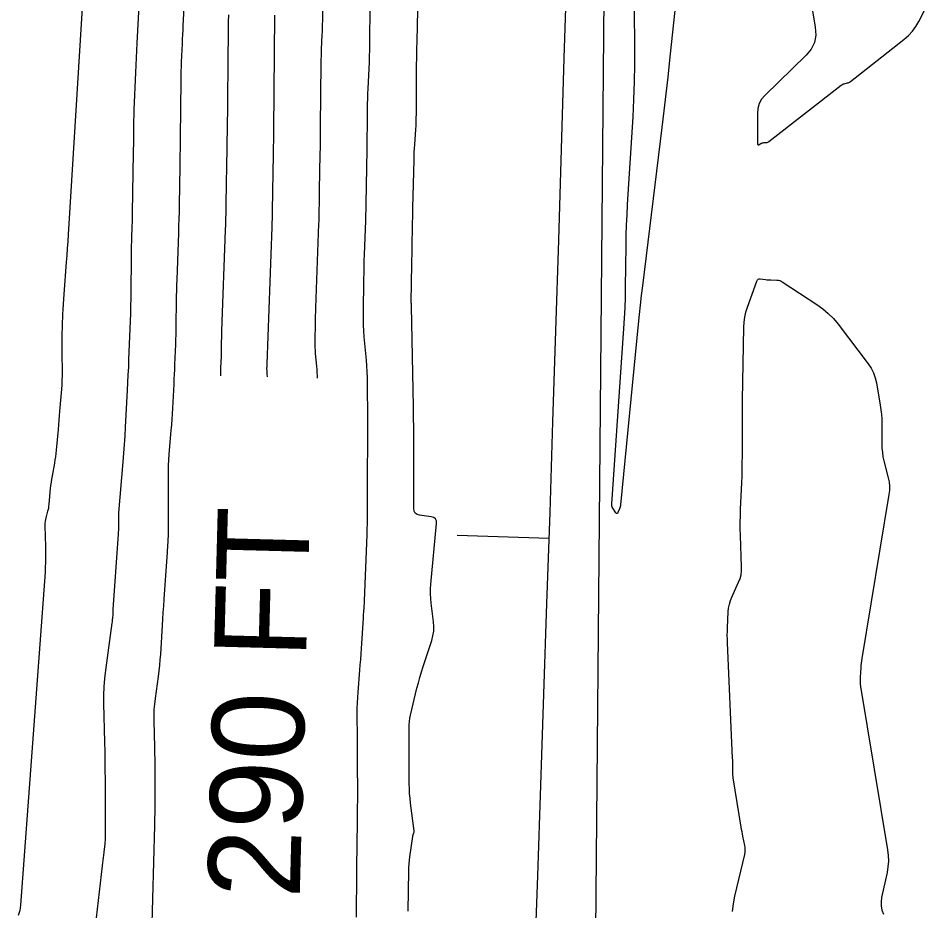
# Model space of a CAD drawing. Extents: x 1768942 to 1774819, y 723037 to 732099.
# Drawn here: x 1770547.7 to 1770607.1, y 731065.2 to 731123.3 of the extents above; entities that cross this region are included whole.
import ezdxf

# ---------------------------------------------------------------- set-up
doc = ezdxf.new("R2010")
doc.units = 0
for name, color, linetype in [('R_Contour Annot', 7, 'Continuous'), ('R_Contours', 7, 'Continuous'), ('R_Horz Alg', 7, 'Continuous')]:
    doc.layers.add(name, color=color, linetype=linetype)

msp = doc.modelspace()

# ---------------------------------------------------------------- linework, layer by layer
at = {"layer": 'R_Contours'}
for points in [[(1770573.122, 731065.186), (1770573.161, 731067.806), (1770573.168, 731068.039), (1770573.182, 731068.271), (1770573.203, 731068.503), (1770573.231, 731068.734), (1770573.41, 731070.056), (1770573.416, 731070.087), (1770573.422, 731070.117), (1770573.431, 731070.147), (1770573.441, 731070.177), (1770573.486, 731070.294), (1770573.495, 731070.324), (1770573.501, 731070.354), (1770573.503, 731070.385), (1770573.501, 731070.415), (1770573.27, 731072.229), (1770573.235, 731072.542), (1770573.21, 731072.856), (1770573.194, 731073.17), (1770573.188, 731073.485), (1770573.182, 731075.423), (1770573.181, 731075.635), (1770573.18, 731075.846), (1770573.179, 731076.058), (1770573.178, 731076.269), (1770573.172, 731077.115), (1770573.177, 731077.326), (1770573.195, 731077.536), (1770573.226, 731077.743), (1770573.269, 731077.95), (1770573.688, 731079.692), (1770573.778, 731080.05), (1770573.876, 731080.406), (1770573.98, 731080.76), (1770574.091, 731081.112), (1770574.649, 731082.812), (1770574.728, 731083.107), (1770574.774, 731083.405), (1770574.786, 731083.706), (1770574.764, 731084.011), (1770574.611, 731085.236), (1770574.581, 731085.542), (1770574.568, 731085.849), (1770574.572, 731086.155), (1770574.592, 731086.463), (1770574.96, 731090.426), (1770574.951, 731090.596), (1770574.891, 731090.724), (1770574.779, 731090.811), (1770574.615, 731090.856), (1770573.856, 731090.954), (1770573.69, 731090.999), (1770573.571, 731091.086), (1770573.501, 731091.215), (1770573.477, 731091.385), (1770573.484, 731093.134), (1770573.485, 731093.49), (1770573.485, 731093.845), (1770573.485, 731094.2), (1770573.484, 731094.556), (1770573.476, 731096.348), (1770573.474, 731096.765), (1770573.47, 731097.182), (1770573.464, 731097.599), (1770573.457, 731098.016), (1770573.333, 731104.563), (1770573.333, 731104.585), (1770573.332, 731104.606), (1770573.33, 731104.627), (1770573.329, 731104.649), (1770573.321, 731104.734), (1770573.319, 731104.756), (1770573.318, 731104.777), (1770573.318, 731104.798), (1770573.318, 731104.82), (1770573.356, 731107.285), (1770573.361, 731107.59), (1770573.366, 731107.895), (1770573.371, 731108.2), (1770573.376, 731108.504), (1770573.396, 731109.723), (1770573.402, 731110.028), (1770573.408, 731110.333), (1770573.414, 731110.638), (1770573.421, 731110.942), (1770573.496, 731114.085), (1770573.504, 731114.332), (1770573.514, 731114.579), (1770573.526, 731114.826), (1770573.542, 731115.073), (1770573.61, 731116.06), (1770573.625, 731116.307), (1770573.636, 731116.554), (1770573.643, 731116.801), (1770573.647, 731117.048), (1770573.662, 731119.699), (1770573.666, 731120.223), (1770573.673, 731120.747), (1770573.682, 731121.272), (1770573.693, 731121.796), (1770573.791, 731125.837)], [(1770590.619, 731125.249), (1770590.129, 731120.565), (1770590.011, 731119.466), (1770589.889, 731118.368), (1770589.761, 731117.27), (1770589.628, 731116.173), (1770588.359, 731105.871), (1770588.284, 731105.251), (1770588.214, 731104.631), (1770588.147, 731104.01), (1770588.085, 731103.388), (1770586.943, 731091.634), (1770586.934, 731091.567), (1770586.92, 731091.501), (1770586.9, 731091.437), (1770586.876, 731091.374), (1770586.767, 731091.125), (1770586.738, 731091.077), (1770586.707, 731091.06), (1770586.673, 731091.072), (1770586.637, 731091.113), (1770586.441, 731091.407), (1770586.402, 731091.476), (1770586.376, 731091.549), (1770586.363, 731091.625), (1770586.362, 731091.705), (1770587.155, 731103.111), (1770587.197, 731103.783), (1770587.229, 731104.454), (1770587.252, 731105.127), (1770587.266, 731105.799), (1770587.301, 731108.491), (1770587.313, 731109.163), (1770587.334, 731109.836), (1770587.364, 731110.508), (1770587.401, 731111.179), (1770587.753, 731116.878), (1770587.813, 731118.01), (1770587.854, 731119.143), (1770587.874, 731120.276), (1770587.875, 731121.41), (1770587.836, 731126.29)], [(1770551.981, 731125.394), (1770550.981, 731109.229), (1770550.952, 731108.774), (1770550.921, 731108.319), (1770550.888, 731107.864), (1770550.854, 731107.41), (1770550.695, 731105.341), (1770550.671, 731105.012), (1770550.651, 731104.682), (1770550.635, 731104.353), (1770550.623, 731104.023), (1770550.579, 731102.622), (1770550.571, 731102.333), (1770550.567, 731102.045), (1770550.566, 731101.756), (1770550.568, 731101.467), (1770550.581, 731100.312), (1770550.582, 731100.023), (1770550.575, 731099.735), (1770550.562, 731099.446), (1770550.543, 731099.158), (1770550.428, 731097.721), (1770550.404, 731097.425), (1770550.379, 731097.129), (1770550.353, 731096.833), (1770550.326, 731096.537), (1770550.199, 731095.182), (1770550.178, 731094.973), (1770550.151, 731094.764), (1770550.12, 731094.556), (1770550.084, 731094.348), (1770549.931, 731093.516), (1770549.895, 731093.31), (1770549.864, 731093.103), (1770549.838, 731092.896), (1770549.817, 731092.688), (1770549.725, 731091.666), (1770549.712, 731091.553), (1770549.694, 731091.441), (1770549.671, 731091.329), (1770549.644, 731091.219), (1770549.523, 731090.779), (1770549.497, 731090.669), (1770549.479, 731090.557), (1770549.469, 731090.445), (1770549.468, 731090.331), (1770549.49, 731089.505), (1770549.494, 731089.329), (1770549.497, 731089.153), (1770549.499, 731088.978), (1770549.5, 731088.802), (1770549.501, 731088.01), (1770549.5, 731087.82), (1770549.495, 731087.63), (1770549.486, 731087.439), (1770549.474, 731087.249), (1770547.874, 731065.58), (1770547.826, 731065.237), (1770547.731, 731064.911)], [(1770599.251, 731124.835), (1770599.618, 731122.7), (1770599.65, 731122.186), (1770599.562, 731121.711), (1770599.353, 731121.275), (1770599.025, 731120.878), (1770596.338, 731118.269), (1770596.121, 731118.015), (1770595.966, 731117.734), (1770595.875, 731117.427), (1770595.846, 731117.094), (1770595.859, 731115.106), (1770595.865, 731115.069), (1770595.88, 731115.049), (1770595.904, 731115.046), (1770595.939, 731115.06), (1770596.097, 731115.152), (1770596.136, 731115.172), (1770596.177, 731115.186), (1770596.219, 731115.195), (1770596.263, 731115.2), (1770596.44, 731115.207), (1770596.483, 731115.212), (1770596.524, 731115.223), (1770596.562, 731115.241), (1770596.598, 731115.265), (1770601.308, 731118.937), (1770601.351, 731118.968), (1770601.398, 731118.993), (1770601.446, 731119.014), (1770601.497, 731119.029), (1770601.707, 731119.08), (1770601.758, 731119.096), (1770601.807, 731119.116), (1770601.853, 731119.142), (1770601.897, 731119.172), (1770605.388, 731121.91), (1770605.678, 731122.164), (1770605.936, 731122.443), (1770606.162, 731122.75), (1770606.356, 731123.082), (1770607.068, 731124.466)], [(1770555.585, 731124.122), (1770555.46, 731121.67), (1770555.436, 731121.192), (1770555.413, 731120.714), (1770555.391, 731120.236), (1770555.37, 731119.758), (1770555.265, 731117.324), (1770555.257, 731117.106), (1770555.25, 731116.889), (1770555.245, 731116.672), (1770555.242, 731116.454), (1770555.23, 731115.266), (1770555.23, 731115.207), (1770555.229, 731115.149), (1770555.228, 731115.091), (1770555.227, 731115.033), (1770555.223, 731114.8), (1770555.222, 731114.741), (1770555.221, 731114.683), (1770555.22, 731114.625), (1770555.219, 731114.566), (1770555.157, 731110.638), (1770555.153, 731110.426), (1770555.148, 731110.214), (1770555.142, 731110.002), (1770555.135, 731109.791), (1770555.104, 731108.944), (1770555.097, 731108.732), (1770555.091, 731108.52), (1770555.087, 731108.309), (1770555.084, 731108.097), (1770555.05, 731105.082), (1770555.042, 731104.582), (1770555.031, 731104.082), (1770555.017, 731103.583), (1770554.999, 731103.083), (1770554.919, 731101.085), (1770554.898, 731100.585), (1770554.876, 731100.086), (1770554.852, 731099.586), (1770554.826, 731099.087), (1770554.698, 731096.692), (1770554.666, 731096.126), (1770554.63, 731095.561), (1770554.589, 731094.996), (1770554.544, 731094.432), (1770554.268, 731091.107), (1770554.26, 731091.001), (1770554.255, 731090.895), (1770554.252, 731090.789), (1770554.251, 731090.682), (1770554.253, 731090.109), (1770554.253, 731090.076), (1770554.253, 731090.043), (1770554.252, 731090.01), (1770554.251, 731089.978), (1770554.246, 731089.847), (1770554.245, 731089.814), (1770554.243, 731089.782), (1770554.241, 731089.749), (1770554.239, 731089.716), (1770553.899, 731084.824), (1770553.894, 731084.75), (1770553.889, 731084.677), (1770553.884, 731084.603), (1770553.879, 731084.529), (1770553.861, 731084.235), (1770553.856, 731084.161), (1770553.849, 731084.088), (1770553.841, 731084.015), (1770553.831, 731083.941), (1770553.406, 731080.868), (1770553.343, 731080.331), (1770553.301, 731079.792), (1770553.282, 731079.252), (1770553.285, 731078.711), (1770553.349, 731076.177), (1770553.362, 731075.574), (1770553.372, 731074.971), (1770553.377, 731074.368), (1770553.38, 731073.765), (1770553.381, 731069.922), (1770553.381, 731069.89), (1770553.381, 731069.858), (1770553.381, 731069.826), (1770553.38, 731069.795), (1770553.377, 731069.668), (1770553.375, 731069.636), (1770553.373, 731069.604), (1770553.371, 731069.573), (1770553.367, 731069.541), (1770553.31, 731069.06), (1770553.299, 731068.969), (1770553.289, 731068.878), (1770553.278, 731068.788), (1770553.267, 731068.697), (1770552.541, 731062.493)], [(1770558.53, 731124.33), (1770558.452, 731122.814), (1770558.438, 731122.518), (1770558.423, 731122.223), (1770558.41, 731121.927), (1770558.397, 731121.631), (1770558.346, 731120.449), (1770558.334, 731120.153), (1770558.325, 731119.857), (1770558.319, 731119.562), (1770558.314, 731119.266), (1770558.276, 731115.512), (1770558.275, 731115.356), (1770558.273, 731115.201), (1770558.27, 731115.045), (1770558.268, 731114.889), (1770558.257, 731114.265), (1770558.254, 731114.109), (1770558.251, 731113.953), (1770558.249, 731113.797), (1770558.246, 731113.641), (1770558.207, 731111.16), (1770558.198, 731110.695), (1770558.187, 731110.23), (1770558.174, 731109.764), (1770558.158, 731109.299), (1770558.048, 731106.286), (1770558.036, 731105.928), (1770558.026, 731105.57), (1770558.019, 731105.211), (1770558.014, 731104.853), (1770557.997, 731103.348), (1770557.992, 731103.025), (1770557.985, 731102.702), (1770557.975, 731102.379), (1770557.964, 731102.056), (1770557.912, 731100.765), (1770557.899, 731100.442), (1770557.884, 731100.119), (1770557.869, 731099.797), (1770557.852, 731099.474), (1770557.77, 731097.926), (1770557.749, 731097.561), (1770557.725, 731097.196), (1770557.699, 731096.831), (1770557.67, 731096.466), (1770557.543, 731094.934), (1770557.516, 731094.557), (1770557.497, 731094.18), (1770557.486, 731093.802), (1770557.483, 731093.424), (1770557.495, 731090.425), (1770557.495, 731090.269), (1770557.493, 731090.113), (1770557.489, 731089.956), (1770557.484, 731089.8), (1770557.459, 731089.176), (1770557.453, 731089.02), (1770557.445, 731088.863), (1770557.436, 731088.707), (1770557.426, 731088.552), (1770557.213, 731085.487), (1770557.183, 731085.058), (1770557.154, 731084.628), (1770557.126, 731084.199), (1770557.099, 731083.769), (1770556.983, 731081.919), (1770556.956, 731081.555), (1770556.923, 731081.193), (1770556.884, 731080.831), (1770556.837, 731080.47), (1770556.637, 731079.026), (1770556.595, 731078.665), (1770556.567, 731078.303), (1770556.554, 731077.94), (1770556.556, 731077.576), (1770556.599, 731075.872), (1770556.608, 731075.466), (1770556.614, 731075.061), (1770556.618, 731074.655), (1770556.619, 731074.25), (1770556.62, 731072.482), (1770556.619, 731072.052), (1770556.615, 731071.622), (1770556.608, 731071.192), (1770556.598, 731070.762), (1770556.412, 731063.612)], [(1770567.207, 731099.862), (1770567.204, 731100.033), (1770567.196, 731100.239), (1770567.184, 731100.444), (1770567.167, 731100.65), (1770567.092, 731101.47), (1770567.076, 731101.675), (1770567.065, 731101.881), (1770567.06, 731102.086), (1770567.061, 731102.292), (1770567.078, 731103.42), (1770567.083, 731103.677), (1770567.089, 731103.933), (1770567.096, 731104.19), (1770567.105, 731104.446), (1770567.305, 731109.905), (1770567.311, 731110.091), (1770567.316, 731110.276), (1770567.321, 731110.462), (1770567.324, 731110.648), (1770567.336, 731111.391), (1770567.339, 731111.577), (1770567.342, 731111.763), (1770567.345, 731111.949), (1770567.348, 731112.135), (1770567.39, 731114.457), (1770567.398, 731114.906), (1770567.404, 731115.355), (1770567.41, 731115.804), (1770567.415, 731116.253), (1770567.457, 731120.37), (1770567.46, 731120.6), (1770567.466, 731120.83), (1770567.473, 731121.06), (1770567.483, 731121.289), (1770567.526, 731122.208), (1770567.536, 731122.438), (1770567.543, 731122.668), (1770567.547, 731122.898), (1770567.549, 731123.128), (1770567.551, 731124.133)], [(1770561.423, 731123.505), (1770561.404, 731123.052), (1770561.399, 731122.939), (1770561.396, 731122.826), (1770561.393, 731122.713), (1770561.392, 731122.599), (1770561.323, 731115.759), (1770561.32, 731115.506), (1770561.317, 731115.252), (1770561.313, 731114.998), (1770561.308, 731114.745), (1770561.29, 731113.73), (1770561.286, 731113.477), (1770561.282, 731113.223), (1770561.277, 731112.969), (1770561.273, 731112.716), (1770561.246, 731110.99), (1770561.239, 731110.617), (1770561.23, 731110.245), (1770561.22, 731109.873), (1770561.207, 731109.501), (1770560.967, 731102.943), (1770560.961, 731102.781), (1770560.957, 731102.619), (1770560.954, 731102.457), (1770560.951, 731102.294), (1770560.944, 731101.614), (1770560.942, 731101.467), (1770560.938, 731101.321), (1770560.934, 731101.175), (1770560.929, 731101.029), (1770560.905, 731100.445), (1770560.899, 731100.299), (1770560.893, 731100.153), (1770560.887, 731100.029)], [(1770563.947, 731099.948), (1770563.945, 731100.128), (1770563.945, 731100.159), (1770563.944, 731100.189), (1770563.942, 731100.22), (1770563.939, 731100.25), (1770563.928, 731100.371), (1770563.926, 731100.402), (1770563.924, 731100.432), (1770563.924, 731100.462), (1770563.924, 731100.493), (1770563.926, 731100.66), (1770563.927, 731100.698), (1770563.928, 731100.736), (1770563.929, 731100.774), (1770563.93, 731100.812), (1770564.256, 731109.703), (1770564.265, 731109.982), (1770564.273, 731110.261), (1770564.28, 731110.54), (1770564.285, 731110.819), (1770564.303, 731111.935), (1770564.307, 731112.214), (1770564.312, 731112.493), (1770564.317, 731112.772), (1770564.322, 731113.051), (1770564.349, 731114.601), (1770564.355, 731114.952), (1770564.36, 731115.303), (1770564.365, 731115.655), (1770564.369, 731116.006), (1770564.444, 731123.483)], [(1770569.747, 731064.792), (1770569.772, 731067.713), (1770569.776, 731068.14), (1770569.78, 731068.567), (1770569.786, 731068.994), (1770569.792, 731069.421), (1770569.817, 731071.13), (1770569.823, 731071.557), (1770569.826, 731071.985), (1770569.828, 731072.412), (1770569.827, 731072.839), (1770569.821, 731074.866), (1770569.819, 731075.254), (1770569.817, 731075.642), (1770569.815, 731076.03), (1770569.813, 731076.418), (1770569.802, 731078.036), (1770569.804, 731078.39), (1770569.813, 731078.744), (1770569.831, 731079.098), (1770569.856, 731079.451), (1770569.972, 731080.864), (1770570, 731081.218), (1770570.027, 731081.571), (1770570.052, 731081.925), (1770570.075, 731082.278), (1770570.198, 731084.246), (1770570.204, 731084.341), (1770570.211, 731084.435), (1770570.217, 731084.53), (1770570.223, 731084.624), (1770570.25, 731085.002), (1770570.256, 731085.096), (1770570.261, 731085.191), (1770570.266, 731085.285), (1770570.27, 731085.38), (1770570.439, 731089.708), (1770570.45, 731090.049), (1770570.458, 731090.39), (1770570.462, 731090.731), (1770570.463, 731091.072), (1770570.458, 731092.436), (1770570.457, 731092.777), (1770570.457, 731093.118), (1770570.459, 731093.459), (1770570.462, 731093.8), (1770570.48, 731095.582), (1770570.484, 731095.992), (1770570.485, 731096.403), (1770570.485, 731096.814), (1770570.484, 731097.224), (1770570.469, 731099.527), (1770570.463, 731099.908), (1770570.449, 731100.289), (1770570.426, 731100.669), (1770570.395, 731101.049), (1770570.255, 731102.569), (1770570.226, 731102.949), (1770570.206, 731103.329), (1770570.197, 731103.71), (1770570.197, 731104.092), (1770570.232, 731106.34), (1770570.24, 731106.735), (1770570.249, 731107.13), (1770570.26, 731107.526), (1770570.274, 731107.921), (1770570.354, 731110.107), (1770570.357, 731110.199), (1770570.359, 731110.292), (1770570.362, 731110.385), (1770570.363, 731110.477), (1770570.369, 731110.848), (1770570.371, 731110.94), (1770570.372, 731111.033), (1770570.374, 731111.125), (1770570.375, 731111.218), (1770570.438, 731114.745), (1770570.444, 731115.076), (1770570.449, 731115.406), (1770570.453, 731115.737), (1770570.457, 731116.067), (1770570.47, 731117.389), (1770570.475, 731117.72), (1770570.483, 731118.05), (1770570.494, 731118.38), (1770570.508, 731118.71), (1770570.589, 731120.427), (1770570.606, 731120.824), (1770570.618, 731121.22), (1770570.625, 731121.616), (1770570.628, 731122.013), (1770570.632, 731123.746)], [(1770594.228, 731065.162), (1770594.285, 731065.668), (1770594.383, 731066.17), (1770595.022, 731068.88), (1770595.048, 731069.028), (1770595.058, 731069.176), (1770595.052, 731069.324), (1770595.029, 731069.472), (1770594.905, 731070.066), (1770594.875, 731070.214), (1770594.846, 731070.363), (1770594.819, 731070.512), (1770594.794, 731070.662), (1770594.276, 731073.857), (1770594.261, 731073.964), (1770594.25, 731074.072), (1770594.244, 731074.18), (1770594.242, 731074.288), (1770594.245, 731074.722), (1770594.244, 731074.83), (1770594.243, 731074.939), (1770594.24, 731075.047), (1770594.236, 731075.155), (1770593.899, 731082.643), (1770593.891, 731082.896), (1770593.888, 731083.149), (1770593.892, 731083.402), (1770593.901, 731083.655), (1770593.95, 731084.666), (1770593.974, 731084.916), (1770594.021, 731085.161), (1770594.091, 731085.4), (1770594.185, 731085.633), (1770594.624, 731086.595), (1770594.717, 731086.835), (1770594.781, 731087.081), (1770594.816, 731087.333), (1770594.821, 731087.59), (1770594.745, 731089.638), (1770594.734, 731090.066), (1770594.731, 731090.494), (1770594.737, 731090.922), (1770594.752, 731091.35), (1770594.83, 731093.069), (1770594.846, 731093.499), (1770594.859, 731093.928), (1770594.866, 731094.358), (1770594.868, 731094.787), (1770594.869, 731096.64), (1770594.87, 731097.092), (1770594.873, 731097.544), (1770594.878, 731097.996), (1770594.885, 731098.448), (1770594.966, 731103.195), (1770594.985, 731103.524), (1770595.031, 731103.848), (1770595.102, 731104.167), (1770595.201, 731104.482), (1770595.812, 731106.194), (1770595.847, 731106.263), (1770595.897, 731106.309), (1770595.96, 731106.332), (1770596.037, 731106.332), (1770596.374, 731106.289), (1770596.459, 731106.279), (1770596.543, 731106.272), (1770596.628, 731106.266), (1770596.713, 731106.263), (1770597.116, 731106.252), (1770597.21, 731106.244), (1770597.299, 731106.222), (1770597.385, 731106.189), (1770597.467, 731106.142), (1770599.713, 731104.668), (1770600.1, 731104.39), (1770600.459, 731104.082), (1770600.791, 731103.745), (1770601.095, 731103.378), (1770603.054, 731100.803), (1770603.246, 731100.518), (1770603.4, 731100.217), (1770603.516, 731099.899), (1770603.594, 731099.564), (1770603.844, 731098.115), (1770603.89, 731097.811), (1770603.922, 731097.505), (1770603.942, 731097.197), (1770603.948, 731096.889), (1770603.947, 731095.6), (1770603.955, 731095.319), (1770603.98, 731095.041), (1770604.023, 731094.764), (1770604.084, 731094.489), (1770604.359, 731093.395), (1770604.414, 731093.121), (1770604.44, 731092.846), (1770604.437, 731092.569), (1770604.405, 731092.292), (1770602.637, 731081.638), (1770602.614, 731081.487), (1770602.595, 731081.334), (1770602.58, 731081.182), (1770602.57, 731081.029), (1770602.535, 731080.416), (1770602.531, 731080.262), (1770602.535, 731080.11), (1770602.547, 731079.958), (1770602.568, 731079.806), (1770604.321, 731069.187), (1770604.364, 731068.818), (1770604.373, 731068.45), (1770604.346, 731068.083), (1770604.285, 731067.717), (1770603.932, 731066.082), (1770603.894, 731065.805), (1770603.901, 731065.533), (1770603.953, 731065.266), (1770604.05, 731065.004)]]:
    msp.add_lwpolyline(points, dxfattribs=at)
at = {"layer": 'R_Horz Alg'}
msp.add_line((1770584.608, 730984.478), (1770588.048, 731363.138), dxfattribs=at)
msp.add_lwpolyline([(1770576.295, 731089.653), (1770582.292, 731089.455)], dxfattribs=at)
msp.add_arc((1759129.36, 731467.219), 11459.16, 355.6942048, 359.4795914, dxfattribs=at)

# ---------------------------------------------------------------- texts
at = {"layer": 'R_Contour Annot'}
msp.add_text('290 FT', height=6, rotation=88.48863, dxfattribs=at).set_placement((1770566.051, 731065.983))

doc.saveas('drawing.dxf')
